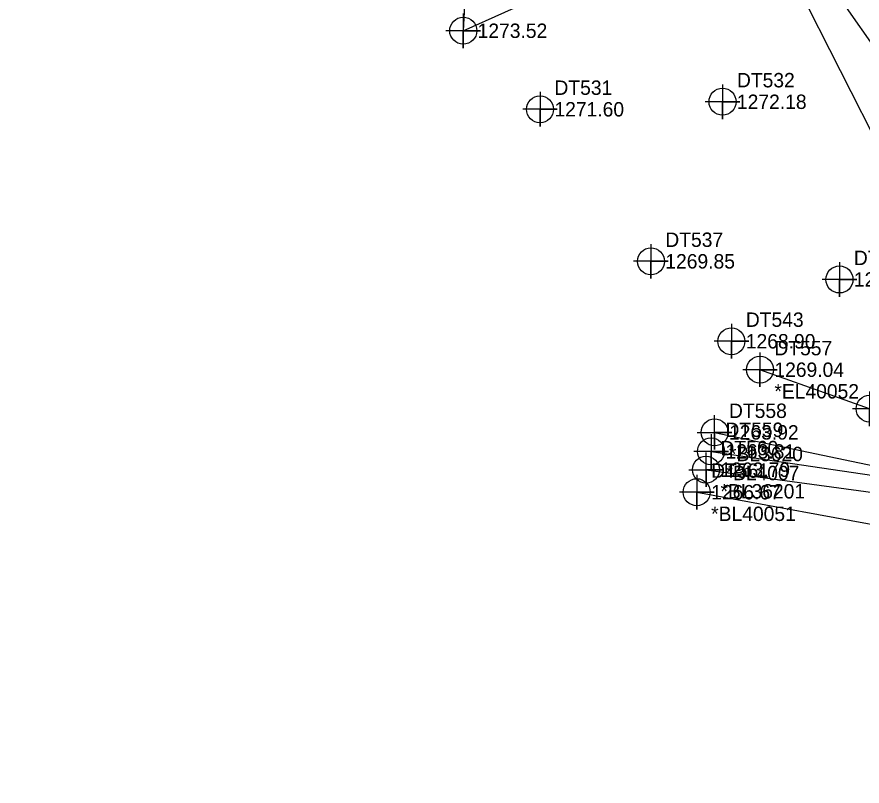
# Model space of a CAD drawing. Extents: x 1391270 to 1392151, y 960049 to 960667.
# Drawn here: x 1391303.8 to 1391450.5, y 960311.3 to 960444.8 of the extents above; entities that cross this region are included whole.
import ezdxf

# ---------------------------------------------------------------- set-up
doc = ezdxf.new("R2010")
doc.units = 0
for name, color, linetype in [('Exist DTM Breakline', 7, 'Continuous'), ('Exist DTM Breakline Cogo Comment', 7, 'Continuous'), ('Exist DTM Breakline Cogo Elevation', 7, 'Continuous'), ('Exist DTM Breakline Cogo Number', 7, 'Continuous'), ('Exist DTM Breakline Cogo Point CELL', 7, 'Continuous'), ('Exist DTM Breakline Underwater', 7, 'Continuous'), ('Exist DTM Breakline Underwater Cogo Comment', 7, 'Continuous'), ('Exist DTM Breakline Underwater Cogo Elevation', 7, 'Continuous'), ('Exist DTM Breakline Underwater Cogo Number', 7, 'Continuous'), ('Exist DTM Breakline Underwater Cogo Point CELL', 7, 'Continuous'), ('Exist DTM Regular Point CELL', 7, 'Continuous'), ('Exist DTM Regular Point Cogo Elevation', 7, 'Continuous'), ('Exist DTM Regular Point Cogo Number', 7, 'Continuous'), ('Exist Hydro Stream or Body of Water', 7, 'Continuous'), ('Exist Hydro Stream or Body of Water Cogo Comment', 7, 'Continuous'), ('Exist Hydro Stream or Body of Water Cogo Elevation', 7, 'Continuous'), ('Exist Hydro Stream or Body of Water Cogo Number', 7, 'Continuous'), ('Exist Hydro Stream or Body of Water Cogo Point CELL', 7, 'Continuous'), ('Exist Roads EOP', 7, 'Continuous')]:
    doc.layers.add(name, color=color, linetype=linetype)

msp = doc.modelspace()

# ---------------------------------------------------------------- linework, layer by layer
at = {"layer": 'Exist DTM Breakline'}
for points in [[(1391316.128, 960578.463), (1391335.373, 960567.825), (1391355.688, 960547.259), (1391385.482, 960507.01), (1391423.359, 960476.875), (1391439.432, 960458.285), (1391460.969, 960427.473), (1391472.339, 960397.865), (1391475.509, 960385.212), (1391483.88, 960383.187), (1391486.523, 960363.38), (1391492.773, 960311.276)], [(1391303.798, 960568.714), (1391337.195, 960549.348), (1391355.915, 960524.922), (1391369.834, 960491.808), (1391382.04, 960457.756), (1391381.24, 960442.404), (1391402.896, 960452.148), (1391420.738, 960472.565), (1391439.191, 960450.264), (1391454.114, 960420.78), (1391463.153, 960401.998), (1391468.38, 960380.734), (1391451.764, 960376.78), (1391432.731, 960383.561)], [(1391421.76, 960362.297), (1391457.674, 960355.681), (1391474.205, 960361.463), (1391477.78, 960353.817), (1391489.16, 960311.358)]]:
    msp.add_lwpolyline(points, dxfattribs=at)
at = {"layer": 'Exist DTM Breakline Cogo Point CELL'}
for points in [[(1391381.24, 960445.404), (1391381.24, 960439.404), (1391381.24, 960442.404), (1391384.24, 960442.404), (1391378.24, 960442.404)], [(1391432.731, 960386.561), (1391432.731, 960380.561), (1391432.731, 960383.561), (1391435.731, 960383.561), (1391429.731, 960383.561)], [(1391451.764, 960379.78), (1391451.764, 960373.78), (1391451.764, 960376.78), (1391454.764, 960376.78), (1391448.764, 960376.78)], [(1391421.76, 960365.297), (1391421.76, 960359.297), (1391421.76, 960362.297), (1391424.76, 960362.297), (1391418.76, 960362.297)]]:
    msp.add_lwpolyline(points, dxfattribs=at)
for centre in [(1391381.24, 960442.404), (1391432.731, 960383.561), (1391451.764, 960376.78), (1391421.76, 960362.297)]:
    msp.add_circle(centre, 2.344, dxfattribs=at)
at = {"layer": 'Exist DTM Breakline Underwater'}
msp.add_lwpolyline([(1391424.242, 960369.381), (1391457.57, 960364.468), (1391474.484, 960370.327)], dxfattribs=at)
at = {"layer": 'Exist DTM Breakline Underwater Cogo Point CELL'}
msp.add_lwpolyline([(1391424.242, 960372.381), (1391424.242, 960366.381), (1391424.242, 960369.381), (1391427.242, 960369.381), (1391421.242, 960369.381)], dxfattribs=at)
msp.add_circle((1391424.242, 960369.381), 2.344, dxfattribs=at)
at = {"layer": 'Exist DTM Regular Point CELL'}
for points in [[(1391426.234, 960433.075), (1391426.234, 960427.075), (1391426.234, 960430.075), (1391429.234, 960430.075), (1391423.234, 960430.075)], [(1391394.566, 960431.771), (1391394.566, 960425.771), (1391394.566, 960428.771), (1391397.566, 960428.771), (1391391.566, 960428.771)], [(1391413.806, 960405.378), (1391413.806, 960399.378), (1391413.806, 960402.378), (1391416.806, 960402.378), (1391410.806, 960402.378)], [(1391446.522, 960402.223), (1391446.522, 960396.223), (1391446.522, 960399.223), (1391449.522, 960399.223), (1391443.522, 960399.223)], [(1391427.773, 960391.5), (1391427.773, 960385.5), (1391427.773, 960388.5), (1391430.773, 960388.5), (1391424.773, 960388.5)]]:
    msp.add_lwpolyline(points, dxfattribs=at)
for centre in [(1391426.234, 960430.075), (1391394.566, 960428.771), (1391413.806, 960402.378), (1391446.522, 960399.223), (1391427.773, 960388.5)]:
    msp.add_circle(centre, 2.344, dxfattribs=at)
at = {"layer": 'Exist Hydro Stream or Body of Water'}
for points in [[(1391424.856, 960372.683), (1391457.478, 960365.839), (1391475.256, 960372.097)], [(1391423.375, 960366.208), (1391457.93, 960361.502), (1391475.159, 960368.812)]]:
    msp.add_lwpolyline(points, dxfattribs=at)
at = {"layer": 'Exist Hydro Stream or Body of Water Cogo Point CELL'}
for points in [[(1391421.856, 960372.683), (1391427.856, 960372.683), (1391424.856, 960372.683), (1391424.856, 960369.683), (1391424.856, 960375.683)], [(1391420.375, 960366.208), (1391426.375, 960366.208), (1391423.375, 960366.208), (1391423.375, 960363.208), (1391423.375, 960369.208)]]:
    msp.add_lwpolyline(points, dxfattribs=at)
for centre in [(1391424.856, 960372.683), (1391423.375, 960366.208)]:
    msp.add_circle(centre, 2.344, dxfattribs=at)
at = {"layer": 'Exist Roads EOP'}
for points in [[(1391558.507, 960409.653), (1391527.113, 960438.384), (1391489.556, 960472.216), (1391453.007, 960506.097), (1391416.783, 960539.246), (1391379.565, 960572.597), (1391343.959, 960605.485)], [(1391497.16, 960311.857), (1391494.199, 960339.333), (1391490.437, 960370.67), (1391484.795, 960409.189), (1391479.352, 960429.561), (1391471.345, 960448.702), (1391460.843, 960466.873), (1391449.093, 960483.056), (1391440.139, 960491.898), (1391403.899, 960524.912), (1391366.94, 960558.603)]]:
    msp.add_spline(points, degree=3, dxfattribs=at)

# ---------------------------------------------------------------- texts
at = {"layer": 'Exist DTM Breakline Cogo Comment'}
for s, p in [('*EL40052', (1391435.231, 960378.561)), ('*BL40051', (1391424.26, 960357.297))]:
    msp.add_text(s, height=2.5, dxfattribs=at).set_placement(p)
at = {"layer": 'Exist DTM Breakline Cogo Elevation'}
for s, p in [('1273.52', (1391383.74, 960441.154)), ('1269.04', (1391435.231, 960382.311)), ('1266.67', (1391424.26, 960361.047))]:
    msp.add_text(s, height=2.5, dxfattribs=at).set_placement(p)
at = {"layer": 'Exist DTM Breakline Cogo Number'}
for s, p in [('DT557', (1391435.231, 960386.061)), ('DT561', (1391424.26, 960364.797))]:
    msp.add_text(s, height=2.5, dxfattribs=at).set_placement(p)
at = {"layer": 'Exist DTM Breakline Underwater Cogo Comment'}
msp.add_text('*BL4007', height=2.5, dxfattribs=at).set_placement((1391426.742, 960364.381))
at = {"layer": 'Exist DTM Breakline Underwater Cogo Elevation'}
msp.add_text('1263.81', height=2.5, dxfattribs=at).set_placement((1391426.742, 960368.131))
at = {"layer": 'Exist DTM Breakline Underwater Cogo Number'}
msp.add_text('DT559', height=2.5, dxfattribs=at).set_placement((1391426.742, 960371.881))
at = {"layer": 'Exist DTM Regular Point Cogo Elevation'}
for s, p in [('1272.18', (1391428.734, 960428.825)), ('1271.60', (1391397.066, 960427.521)), ('1269.85', (1391416.306, 960401.128)), ('1270.06', (1391449.022, 960397.973)), ('1268.90', (1391430.273, 960387.25))]:
    msp.add_text(s, height=2.5, dxfattribs=at).set_placement(p)
at = {"layer": 'Exist DTM Regular Point Cogo Number'}
for s, p in [('DT532', (1391428.734, 960432.575)), ('DT531', (1391397.066, 960431.271)), ('DT537', (1391416.306, 960404.878)), ('DT542', (1391449.022, 960401.723)), ('DT543', (1391430.273, 960391))]:
    msp.add_text(s, height=2.5, dxfattribs=at).set_placement(p)
at = {"layer": 'Exist Hydro Stream or Body of Water Cogo Comment'}
for s, p in [('*BL3620', (1391427.356, 960367.683)), ('*BL36201', (1391425.875, 960361.208))]:
    msp.add_text(s, height=2.5, dxfattribs=at).set_placement(p)
at = {"layer": 'Exist Hydro Stream or Body of Water Cogo Elevation'}
for s, p in [('1263.92', (1391427.356, 960371.433)), ('1263.79', (1391425.875, 960364.958))]:
    msp.add_text(s, height=2.5, dxfattribs=at).set_placement(p)
at = {"layer": 'Exist Hydro Stream or Body of Water Cogo Number'}
for s, p in [('DT558', (1391427.356, 960375.183)), ('DT560', (1391425.875, 960368.708))]:
    msp.add_text(s, height=2.5, dxfattribs=at).set_placement(p)

doc.saveas('drawing.dxf')
